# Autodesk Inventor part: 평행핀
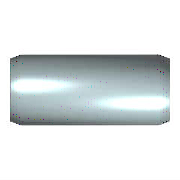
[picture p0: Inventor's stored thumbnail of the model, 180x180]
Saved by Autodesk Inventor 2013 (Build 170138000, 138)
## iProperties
IsCustomPart: 0
Created: 2009-02
Part Number: 평행핀
Material: 강, 연강
Description: 평행 핀
Document SubType Name: Modeling
Standard: KS B 1320
Designer: KYOUNG IL JANG
Standards Organization: KS
Language: ko-KR
Size Designation: B 5 x  20
Categories: <MemberInstance><Categories><Category DisplayName="조임쇠" InternalName="e4da775c-781d-43d5-af7c-5136215cf5a6" Mnemonic="FSTN"><Category DisplayName="핀" InternalNa
Density: 7.86 g/cm^3
Mass: 3.06605 g
Surface Area: 3.46755 cm^2
Volume: 0.390082 cm^3
Author: KYOUNG IL JANG
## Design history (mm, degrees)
sketch "스케치"
  geometry: C1 r 2.5 at (0, 0); 1 further point
  constraints: 1 centre point, 1 coincident
  dimensions: "d1" = 5 diameter of C1 (= NND)
extrude "본체" new body sketch "스케치" distance "d2" = 20 (= NLG); taper "d3" = 0 deg
chamfer "스케치2" distance "d8" = 0.8 (= PHH); stored, may be unused: angle "d9" = 15 deg (= FAWI), second distance "d12" = 0.8 (= PHH)
body "Solid1"
chamfer "모따기1" distance "d4" = 0.8 (= PHH); stored, may be unused: angle "d5" = 15 deg (= FAWI), second distance "d11" = 0.8 (= PHH)
other parameters: "NND" = 5 [user parameter; used in 1 equation term], "NLG" = 20 [user parameter; used in 1 equation term], "PHH" = 0.8 [user parameter; used in 4 equation terms], "FAWI" = 15 deg [user parameter; used in 2 equation terms], "d13" = 0, "d15" = 0, "d16" = 0, "KAH" = 0.63 [user parameter]
